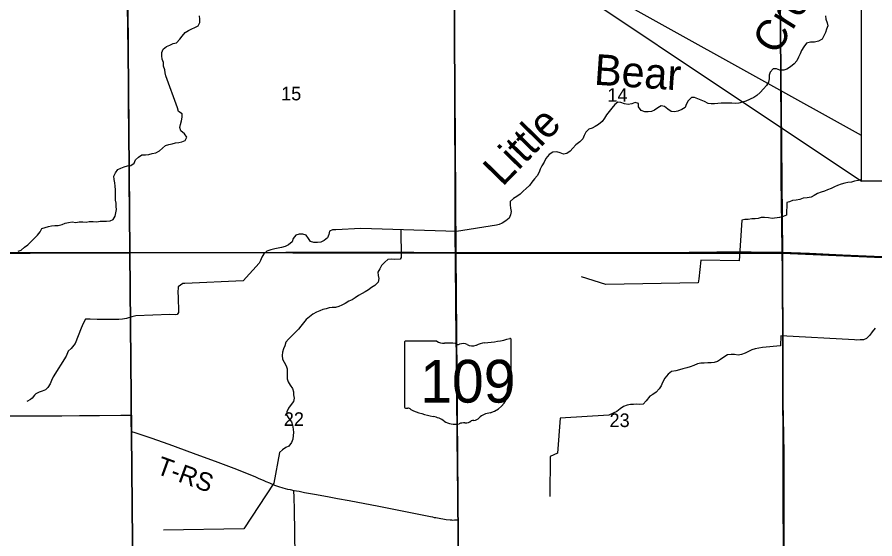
# Model space of a CAD drawing. Extents: x 0 to 34, y 0 to 22.
# Drawn here: x 25.546 to 28.195, y 17.753 to 19.362 of the extents above; entities that cross this region are included whole.
import ezdxf

# ---------------------------------------------------------------- set-up
doc = ezdxf.new("R2010")
doc.units = 0
for name, color, linetype in [('GM_X_County_Road', 7, 'Continuous'), ('GM_X_Minor_River', 7, 'Continuous'), ('GM_X_Minor_River_Text', 7, 'Continuous'), ('GM_X_Section', 7, 'Continuous'), ('GM_X_Section_Text', 7, 'Continuous'), ('GM_X_State_Location', 7, 'Continuous'), ('GM_X_State_Route', 7, 'Continuous'), ('GM_X_State_Shield', 7, 'Continuous'), ('GM_X_Township_Road', 7, 'Continuous'), ('GM_X_Township_Road_Text', 7, 'Continuous'), ('SH_Data', 7, 'Continuous')]:
    doc.layers.add(name, color=color, linetype=linetype)

msp = doc.modelspace()

# ---------------------------------------------------------------- linework, layer by layer
at = {"layer": 'GM_X_County_Road'}
for points in [[(25.1452, 18.632), (25.2015, 18.6323), (25.2574, 18.6324), (25.304, 18.6331), (25.4128, 18.6328), (25.5216, 18.6336), (25.5869, 18.6341), (25.7485, 18.6348), (25.8945, 18.6357)], [(25.8945, 18.6357), (25.9444, 18.6361), (26.1216, 18.6366), (26.3765, 18.6374), (26.535, 18.6374), (26.5848, 18.6374), (26.6407, 18.6371), (26.7713, 18.6368), (26.8998, 18.6366)], [(26.8998, 18.6366), (26.9081, 18.6366), (27.0324, 18.6366), (27.1692, 18.6362), (27.2469, 18.636), (27.3464, 18.6363), (27.4179, 18.6363), (27.4925, 18.6361), (27.508, 18.6361), (27.536, 18.6367), (27.707, 18.6379), (27.8127, 18.6379), (27.9029, 18.6374), (27.9087, 18.6372)], [(27.9087, 18.6372), (27.993, 18.6341), (28.0955, 18.6295), (28.2911, 18.6207), (28.3284, 18.6191), (28.3967, 18.6161), (28.5551, 18.6091), (28.6296, 18.6055), (28.6948, 18.6022), (28.7911, 18.5974), (28.8252, 18.5957), (28.8749, 18.5932), (28.9028, 18.5928)]]:
    msp.add_lwpolyline(points, dxfattribs=at)
at = {"layer": 'GM_X_Minor_River'}
msp.add_line((27.9229, 18.7904), (27.9225, 18.7514), dxfattribs=at)
for points in [[(25.5493, 18.6401), (25.5588, 18.6438), (25.5695, 18.6532), (25.5791, 18.6599), (25.5894, 18.6697), (25.5994, 18.6794), (25.609, 18.69), (25.6178, 18.7001), (25.6228, 18.71), (25.6331, 18.7133), (25.643, 18.7166), (25.6529, 18.7184), (25.6624, 18.7191), (25.6726, 18.7193), (25.6851, 18.7226), (25.695, 18.7263), (25.7053, 18.7289), (25.7163, 18.731), (25.728, 18.7287), (25.7379, 18.7308), (25.7489, 18.7307), (25.7595, 18.7299), (25.769, 18.7317), (25.7808, 18.7319), (25.7925, 18.7307), (25.8024, 18.7329), (25.8123, 18.7331), (25.8225, 18.7334), (25.8335, 18.7344), (25.843, 18.7378), (25.8496, 18.7487), (25.8508, 18.7589), (25.8528, 18.7688), (25.8522, 18.7787), (25.8519, 18.7885), (25.8501, 18.798), (25.8504, 18.8299), (25.8487, 18.8409), (25.848, 18.8512), (25.8462, 18.8618), (25.8448, 18.8721), (25.8499, 18.8819), (25.8572, 18.8925), (25.8671, 18.8969), (25.8766, 18.9006), (25.8876, 18.9032), (25.8975, 18.905), (25.9074, 18.9121), (25.9117, 18.9219), (25.9213, 18.9302), (25.9312, 18.9373), (25.9426, 18.9375), (25.9528, 18.939), (25.9635, 18.9415), (25.9749, 18.9437), (25.9856, 18.95), (25.9951, 18.9583), (26.0047, 18.9662), (26.0153, 18.9695), (26.0252, 18.972), (26.0359, 18.9746), (26.0457, 18.9756), (26.0552, 18.9778), (26.0648, 18.9823), (26.0706, 18.9925), (26.0631, 19.0028), (26.0518, 19.012), (26.0489, 19.0219), (26.0513, 19.0317), (26.0537, 19.0423), (26.056, 19.0537), (26.0562, 19.0639), (26.0449, 19.0717), (26.042, 19.0831), (26.0055, 19.181), (26.0033, 19.1905), (26.0027, 19.2003), (25.9979, 19.2114), (25.998, 19.2228), (25.9943, 19.2331), (25.9929, 19.2433), (25.9934, 19.2532), (25.9969, 19.2634), (26.008, 19.2716), (26.0175, 19.2761), (26.0286, 19.2809), (26.0388, 19.2827), (26.0484, 19.294), (26.0561, 19.3038), (26.0653, 19.3147), (26.0752, 19.3215), (26.0855, 19.3259), (26.095, 19.33), (26.105, 19.3356), (26.1104, 19.3458), (26.1101, 19.3564), (26.1098, 19.3663)], [(28.0424, 19.3662), (28.0438, 19.3563), (28.0478, 19.3449), (28.0496, 19.3354), (28.0454, 19.3251), (28.043, 19.3149), (28.0379, 19.3047), (28.0321, 19.2949), (28.0211, 19.2882), (28.0089, 19.2857), (27.9964, 19.2854), (27.9839, 19.2817), (27.9754, 19.2712), (27.9681, 19.2599), (27.9642, 19.2497), (27.9591, 19.2387), (27.9545, 19.2281), (27.946, 19.2183), (27.9349, 19.2086), (27.9235, 19.2023), (27.9136, 19.1989), (27.9019, 19.1987), (27.8917, 19.2026), (27.881, 19.2027), (27.8718, 19.1929), (27.8691, 19.1831), (27.8686, 19.1721), (27.8666, 19.1622), (27.8608, 19.1513), (27.8512, 19.1415), (27.8405, 19.1298), (27.8305, 19.1204), (27.821, 19.1148), (27.7966, 19.1029), (27.7863, 19.0996), (27.7753, 19.0971), (27.7654, 19.096), (27.7537, 19.0965), (27.7438, 19.097), (27.7306, 19.0975), (27.7207, 19.0972), (27.7101, 19.0958), (27.7002, 19.0952), (27.6896, 19.0953), (27.6798, 19.0961), (27.6688, 19.1019), (27.6586, 19.1062), (27.6488, 19.1108), (27.6383, 19.1147), (27.6284, 19.1141), (27.6188, 19.1047), (27.6126, 19.0934), (27.6091, 19.0835), (27.5988, 19.0772), (27.587, 19.0727), (27.5767, 19.0702), (27.5661, 19.0718), (27.5556, 19.0788), (27.5451, 19.0868), (27.5349, 19.0884), (27.5253, 19.0828), (27.5146, 19.0757), (27.5051, 19.0717), (27.4952, 19.0699), (27.4842, 19.07), (27.4733, 19.0743), (27.4651, 19.0853), (27.4648, 19.0956), (27.455, 19.0995), (27.4447, 19.0947), (27.4329, 19.0925), (27.4223, 19.0945), (27.411, 19.0995), (27.4012, 19.0996), (27.3916, 19.0925), (27.3824, 19.0816), (27.3747, 19.0718), (27.3659, 19.0609), (27.3601, 19.0503), (27.3524, 19.0405), (27.3417, 19.0311), (27.3318, 19.0252), (27.3222, 19.0196), (27.3116, 19.0163), (27.302, 19.0073), (27.297, 18.9974), (27.2931, 18.9872), (27.2839, 18.9774), (27.272, 18.9681), (27.2628, 18.9583)], [(27.2628, 18.9583), (27.2544, 18.9485), (27.2437, 18.9418), (27.2338, 18.9396), (27.2236, 18.9435), (27.2126, 18.947), (27.2001, 18.946), (27.1894, 18.9385), (27.1794, 18.9261), (27.1736, 18.9148), (27.1671, 18.9038), (27.1613, 18.8936), (27.1585, 18.8838), (27.1523, 18.8732), (27.1443, 18.8631), (27.1362, 18.8533), (27.1285, 18.8435), (27.1182, 18.8341), (27.1086, 18.8258), (27.0994, 18.8161), (27.0899, 18.8093), (27.0788, 18.8026), (27.0692, 18.794), (27.0691, 18.7833), (27.0698, 18.7731), (27.0723, 18.7632), (27.0703, 18.753), (27.0657, 18.7424), (27.0557, 18.7341), (27.0446, 18.727), (27.0351, 18.7226), (27.0271, 18.7204)], [(28.1535, 18.8618), (28.1534, 18.8618), (28.1439, 18.8588), (28.1325, 18.8567), (28.123, 18.8537), (28.1116, 18.852), (28.1021, 18.8498), (28.0911, 18.8468), (28.0801, 18.8432), (28.0705, 18.8387), (28.0602, 18.8342), (28.0488, 18.8298), (28.0393, 18.8257), (28.0287, 18.8224), (28.0176, 18.818), (28.0073, 18.8124), (27.9978, 18.8075), (27.986, 18.805), (27.9739, 18.804), (27.9632, 18.8003), (27.9518, 18.7981), (27.9408, 18.7963), (27.9313, 18.793), (27.9229, 18.7904)], [(27.9225, 18.7514), (27.9122, 18.7469), (27.9008, 18.7444), (27.8781, 18.7408), (27.8667, 18.7432), (27.8538, 18.7444), (27.8443, 18.7442), (27.8348, 18.7416), (27.825, 18.7402), (27.8147, 18.7399), (27.8037, 18.7385), (27.7939, 18.7378), (27.7844, 18.7356), (27.7851, 18.7356)], [(27.7844, 18.7356), (27.7762, 18.6101), (27.6572, 18.6128), (27.6517, 18.5552), (27.6489, 18.543), (27.3645, 18.5371), (27.2893, 18.5614)], [(26.53, 18.7059), (26.5205, 18.7057), (26.5106, 18.7023), (26.5086, 18.6917), (26.5043, 18.6819), (26.4944, 18.6733), (26.4841, 18.6681), (26.4742, 18.667), (26.4621, 18.6675), (26.4523, 18.6699), (26.4459, 18.6798), (26.4384, 18.6898), (26.4282, 18.6925), (26.4169, 18.693), (26.407, 18.6901), (26.3989, 18.6795), (26.3961, 18.6689), (26.3847, 18.6596), (26.3736, 18.6547), (26.3626, 18.6514), (26.3527, 18.65), (26.3425, 18.6478), (26.3299, 18.6449), (26.3177, 18.6405), (26.3082, 18.6318), (26.3024, 18.622), (26.2981, 18.6118), (26.2935, 18.6035)], [(27.0271, 18.7204), (26.9026, 18.7011), (26.6074, 18.7105), (26.53, 18.7059)], [(26.7316, 18.7065), (26.7326, 18.6208)], [(26.7326, 18.6208), (26.7295, 18.6162), (26.7129, 18.6149), (26.7023, 18.6158), (26.6913, 18.6144), (26.6813, 18.6061), (26.6717, 18.5964), (26.6663, 18.5858), (26.6605, 18.5756), (26.6612, 18.5657), (26.6637, 18.5558), (26.6613, 18.5452), (26.651, 18.5347), (26.6411, 18.5287), (26.6315, 18.5216), (26.6208, 18.5153), (26.6113, 18.5093), (26.601, 18.5037), (26.5907, 18.4966), (26.5807, 18.4902), (26.5705, 18.4862), (26.5594, 18.4791), (26.5491, 18.4735), (26.5396, 18.4694), (26.5297, 18.4661), (26.5195, 18.4669), (26.51, 18.4655), (26.5005, 18.4626), (26.4902, 18.4604), (26.4807, 18.4559), (26.4704, 18.4519), (26.4597, 18.4463), (26.4494, 18.4377), (26.4394, 18.4298), (26.4302, 18.4196), (26.4229, 18.4091), (26.4149, 18.3993), (26.4053, 18.3895), (26.3945, 18.3794), (26.3842, 18.3692), (26.3765, 18.3594), (26.3726, 18.3488), (26.3687, 18.339), (26.3663, 18.3284), (26.3643, 18.3186), (26.3661, 18.3075), (26.3713, 18.2976), (26.3776, 18.2869), (26.3802, 18.277), (26.3801, 18.266), (26.3803, 18.2562), (26.3806, 18.2467), (26.3832, 18.2372), (26.3891, 18.2265), (26.3966, 18.2162), (26.3995, 18.2063), (26.3998, 18.1968), (26.4016, 18.1869), (26.3996, 18.177), (26.3926, 18.1669), (26.3842, 18.1556), (26.3791, 18.145), (26.3786, 18.1355), (26.3857, 18.1244), (26.3932, 18.1137), (26.3969, 18.1034), (26.3986, 18.0917), (26.4, 18.0814), (26.3988, 18.0712), (26.3975, 18.0606), (26.3936, 18.05), (26.3856, 18.039), (26.3757, 18.035), (26.3657, 18.0271), (26.3561, 18.0192)], [(26.2935, 18.6035), (26.2443, 18.549), (26.0646, 18.5405), (26.0577, 18.5402), (26.0432, 18.5305), (26.043, 18.5123), (26.044, 18.5001), (26.0443, 18.4515), (26.0408, 18.4451), (26.0343, 18.4444), (26.0177, 18.4446), (25.913, 18.4407), (25.9001, 18.4381), (25.8837, 18.433), (25.8719, 18.4301), (25.8609, 18.4294), (25.7931, 18.4293), (25.7722, 18.4307), (25.7571, 18.4308), (25.7505, 18.4176), (25.7439, 18.4025), (25.7255, 18.356), (25.7129, 18.3402), (25.7044, 18.3323), (25.6974, 18.316), (25.6573, 18.2523), (25.653, 18.2413), (25.6488, 18.2311), (25.6414, 18.2194), (25.6341, 18.2123), (25.6239, 18.2082), (25.614, 18.2057), (25.6037, 18.2001), (25.5999, 18.1963), (25.5929, 18.1869), (25.5872, 18.1824), (25.5765, 18.1768)], [(28.1963, 18.4029), (28.1867, 18.3916), (28.1791, 18.381), (28.1691, 18.3709), (28.1596, 18.3668), (28.1493, 18.3669), (28.1397, 18.3662), (28.1319, 18.3667)], [(28.1319, 18.3667), (27.9049, 18.3792), (27.9031, 18.3485), (27.8477, 18.3429)], [(27.8477, 18.3429), (27.8249, 18.3394), (27.8146, 18.3357), (27.8043, 18.3312), (27.7948, 18.3252), (27.783, 18.3219), (27.7731, 18.3194), (27.7614, 18.3218), (27.7508, 18.3211), (27.7398, 18.3201), (27.7283, 18.313), (27.7184, 18.3066), (27.7088, 18.2999), (27.699, 18.2974), (27.6895, 18.2959), (27.6792, 18.296), (27.6679, 18.295), (27.6572, 18.2947), (27.6474, 18.2929), (27.6356, 18.2881), (27.6245, 18.2837), (27.6142, 18.2804), (27.6017, 18.2771), (27.5914, 18.2738), (27.58, 18.2712), (27.5675, 18.2691), (27.5568, 18.2604), (27.5468, 18.2484), (27.5391, 18.2352), (27.5348, 18.225), (27.529, 18.2152), (27.5198, 18.2054), (27.5095, 18.1979), (27.4999, 18.1927), (27.4892, 18.1788), (27.48, 18.1686), (27.4693, 18.1672), (27.4595, 18.1684), (27.4496, 18.1678), (27.4401, 18.1671), (27.4299, 18.1657), (27.4189, 18.1612), (27.4085, 18.1541), (27.3982, 18.1455), (27.3734, 18.1347)], [(27.3734, 18.1347), (27.2236, 18.1252), (27.2148, 18.0168), (27.1927, 18.0064), (27.1914, 17.8834)], [(26.3561, 18.0192), (26.3392, 17.9249), (26.2463, 17.7839), (25.9979, 17.7795)]]:
    msp.add_lwpolyline(points, dxfattribs=at)
at = {"layer": 'GM_X_Section'}
for points in [[(24.8865, 19.6346), (25.8865, 19.646), (25.8948, 18.6366), (24.8949, 18.6346)], [(25.8865, 19.646), (26.8952, 19.6361), (26.901, 18.6343), (25.8948, 18.6366)], [(26.8952, 19.6361), (27.9, 19.6399), (27.9094, 18.6339), (26.901, 18.6343)], [(24.8949, 18.6346), (25.8948, 18.6366), (25.9035, 17.634), (24.9025, 17.6286)], [(25.8948, 18.6366), (26.901, 18.6343), (26.9089, 17.6314), (25.9035, 17.634)], [(26.901, 18.6343), (27.9094, 18.6339), (27.9132, 17.6317), (26.9089, 17.6314)], [(27.9094, 18.6339), (28.9031, 18.5906), (28.914, 17.6074), (28.9139, 17.6013), (27.9132, 17.6317)]]:
    msp.add_lwpolyline(points, close=True, dxfattribs=at)
msp.add_lwpolyline([(28.9007, 18.8568), (28.9028, 18.5982), (28.9031, 18.5906), (27.9094, 18.6339), (27.9, 19.6399), (28.1535, 19.6259)], dxfattribs=at)
at = {"layer": 'GM_X_State_Route'}
msp.add_lwpolyline([(26.9096, 17.635), (26.9094, 17.655), (26.9085, 17.7701), (26.9083, 17.8012), (26.9083, 17.8111), (26.9082, 17.8353), (26.9065, 17.9628), (26.9055, 18.0809), (26.9042, 18.1835), (26.9037, 18.2208), (26.9015, 18.4664), (26.8999, 18.6187), (26.8998, 18.6366), (26.8995, 18.6685), (26.8989, 18.8457), (26.8988, 18.8923), (26.8987, 18.9451), (26.8983, 18.9886), (26.8978, 19.0539), (26.8976, 19.1565), (26.8966, 19.4239)], dxfattribs=at)
at = {"layer": 'GM_X_State_Shield'}
for p, q in [((26.7426, 18.3592), (26.7426, 18.1591)), ((26.8424, 18.3627), (26.7459, 18.3627)), ((27.0722, 18.2629), (27.0722, 18.3676)), ((27.0722, 18.263), (27.0722, 18.2629))]:
    msp.add_line(p, q, dxfattribs=at)
for centre, major_axis, start_param, end_param in [((26.7464, 18.3596), (0.00382, 0), 1.712693, 3.28349), ((26.8654, 18.3859), (0.037, 0), 4.042523, 4.731795), ((26.8777, 18.2503), (0.133, 0), 1.404758, 1.657858), ((26.9079, 18.3607), (0.0107, 0), 3.836095, 5.185415), ((26.9235, 18.3376), (0.0222, 0), 0.950623, 2.079405), ((26.9994, 18.3015), (0.0703, 0), 1.699011, 2.107814), ((26.9548, 18.6355), (0.3495, 0), 4.814394, 5.042369), ((27.0686, 18.3681), (0.00367, 0), 6.141152, 7.989035), ((26.9522, 18.3693), (0.0267, 0), 4.081561, 5.145723), ((27.0714, 18.2553), (0.00568, 0), 1.883978, 3.671073), ((27.0353, 18.242), (0.0341, 0), 5.934695, 6.695948), ((27.0683, 18.2625), (0.00393, 0), 5.05454, 6.418171), ((27.0854, 18.2191), (0.0248, 0), 2.387724, 3.262537), ((26.9744, 18.2058), (0.0874, 0), 5.101752, 6.440018), ((26.7465, 18.1587), (0.00385, 0), 3.00124, 4.508301), ((26.747, 18.1791), (0.0294, 0), 4.665946, 4.897461), ((26.753, 18.1476), (0.0106, 0), 0.519207, 1.627899), ((26.8869, 18.3274), (0.2524, 0), 4.195997, 4.488961), ((26.8116, 18.0692), (0.079, 0), 0.823519, 1.323587), ((26.897, 18.1466), (0.0501, 0), 4.026481, 4.996735), ((26.9297, 18.1316), (0.0267, 0), 4.691044, 5.507374), ((26.9538, 18.1122), (0.00752, 0), 1.147584, 2.315152), ((26.9506, 18.1397), (0.0282, 0), 4.937069, 5.64225), ((27.0113, 18.1029), (0.0479, 0), 1.647645, 2.488434), ((26.926, 18.0774), (0.0412, 0), 1.495662, 1.94098)]:
    msp.add_ellipse(centre, major_axis=major_axis, ratio=0.8, start_param=start_param, end_param=end_param, dxfattribs=at)
at = {"layer": 'GM_X_Township_Road'}
for points in [[(25.8945, 18.6357), (25.8943, 18.6408), (25.8945, 18.6467), (25.8942, 18.6809), (25.8935, 18.7649), (25.8933, 18.7742), (25.8928, 18.8394), (25.8927, 18.9047), (25.8922, 18.9576), (25.8918, 19.0011), (25.8907, 19.0975), (25.8899, 19.1877), (25.8882, 19.3277), (25.8873, 19.3992), (25.8868, 19.4614), (25.8851, 19.5921), (25.8841, 19.6375)], [(27.9087, 18.6372), (27.9072, 18.7261), (27.9063, 18.7883), (27.9059, 18.8629), (27.9059, 18.8806), (27.9055, 18.9693), (27.9052, 19.0843), (27.905, 19.1153), (27.9043, 19.1961), (27.9033, 19.3142), (27.9021, 19.4106), (27.9013, 19.5367), (27.9007, 19.6113), (27.9008, 19.6379)], [(25.8986, 18.1345), (25.8988, 18.1526), (25.8982, 18.2677), (25.8977, 18.3206), (25.8973, 18.3735), (25.895, 18.5694), (25.8951, 18.6036), (25.8945, 18.6223), (25.8946, 18.6315), (25.8945, 18.6357)], [(27.916, 17.6355), (27.9156, 17.6507), (27.9153, 17.7626), (27.9149, 17.8559), (27.9148, 17.8838), (27.9146, 17.9274), (27.9144, 18.0175), (27.9131, 18.1263), (27.9122, 18.1729), (27.9118, 18.2288), (27.9113, 18.3594), (27.9106, 18.4246), (27.9102, 18.4961), (27.9096, 18.5831), (27.9088, 18.636), (27.9087, 18.6372)], [(25.3982, 18.1319), (25.5718, 18.1326), (25.6847, 18.1327), (25.7391, 18.1333), (25.8007, 18.1333), (25.8669, 18.1342), (25.8986, 18.1345)], [(25.9, 18.0837), (25.9001, 18.0871), (25.8998, 18.0932), (25.8995, 18.0962), (25.8989, 18.099), (25.8985, 18.105), (25.8986, 18.1206), (25.8986, 18.1345)], [(25.9025, 17.6344), (25.9026, 17.6548), (25.9024, 17.6703), (25.9022, 17.7605), (25.9014, 17.8911), (25.9, 18.0715), (25.9, 18.0837)], [(25.9, 18.0837), (25.9094, 18.0808), (25.9591, 18.0643), (26.0144, 18.0448), (26.0901, 18.0172), (26.1659, 17.9893), (26.216, 17.9706), (26.2448, 17.9594), (26.2719, 17.9485), (26.2799, 17.945), (26.2926, 17.9395), (26.3061, 17.9338), (26.3145, 17.9301), (26.3252, 17.9255), (26.3407, 17.9188), (26.3531, 17.9142), (26.3672, 17.9102), (26.3814, 17.9066), (26.3897, 17.9048), (26.4012, 17.9022)], [(26.4012, 17.9022), (26.417, 17.8996), (26.434, 17.8962), (26.4703, 17.8896), (26.5103, 17.8824), (26.5359, 17.8775), (26.5714, 17.8712), (26.6633, 17.8539), (26.7922, 17.8284), (26.8224, 17.822), (26.8286, 17.8206), (26.8346, 17.8192), (26.8393, 17.8183), (26.8447, 17.8174), (26.8713, 17.813), (26.8831, 17.8113), (26.8852, 17.8111), (26.8875, 17.811), (26.8901, 17.8108), (26.8971, 17.811), (26.9019, 17.811), (26.9083, 17.8111)], [(26.4066, 17.6348), (26.4065, 17.638), (26.405, 17.7001), (26.4027, 17.8429), (26.402, 17.8802), (26.4012, 17.9022)]]:
    msp.add_lwpolyline(points, dxfattribs=at)
at = {"layer": 'SH_Data'}
for points in [[(26.8948, 19.6968), (28.1535, 18.8568), (28.1535, 18.9968)], [(28.1535, 19.6968), (29.8322, 19.6968), (29.8322, 18.8568), (28.1535, 18.8568)]]:
    msp.add_lwpolyline(points, close=True, dxfattribs=at)

# ---------------------------------------------------------------- texts
at = {"layer": 'GM_X_Minor_River_Text'}
for s, height, rotation, p in [('Creek', 0.09475, 57.9626, (27.8917, 19.2419)), ('Bear', 0.09476, 356.1302, (27.3263, 19.1543)), ('Little', 0.09475, 45.8125, (27.0448, 18.8371))]:
    msp.add_text(s, height=height, rotation=rotation, dxfattribs=at).set_placement(p)
at = {"layer": 'GM_X_Section_Text'}
for s, p in [('15', (26.3615, 19.1057)), ('14', (27.369, 19.1013)), ('22', (26.3698, 18.1013)), ('23', (27.3756, 18.0977))]:
    msp.add_text(s, height=0.04186, rotation=0, dxfattribs=at).set_placement(p)
at = {"layer": 'GM_X_State_Location'}
msp.add_text('109', height=0.000189, rotation=0, dxfattribs=at).set_placement((26.8369, 18.2321))
for s in ['s', 'r']:
    msp.add_text(s, height=0.000189, dxfattribs=at).set_placement((26.9037, 18.2459))
at = {"layer": 'GM_X_State_Shield'}
msp.add_text('109', height=0.13184, dxfattribs=at).set_placement((26.7911, 18.1732))
at = {"layer": 'GM_X_Township_Road_Text'}
msp.add_text('T-RS', height=0.05682, rotation=340.0716, dxfattribs=at).set_placement((25.9727, 17.955))

doc.saveas('drawing.dxf')
